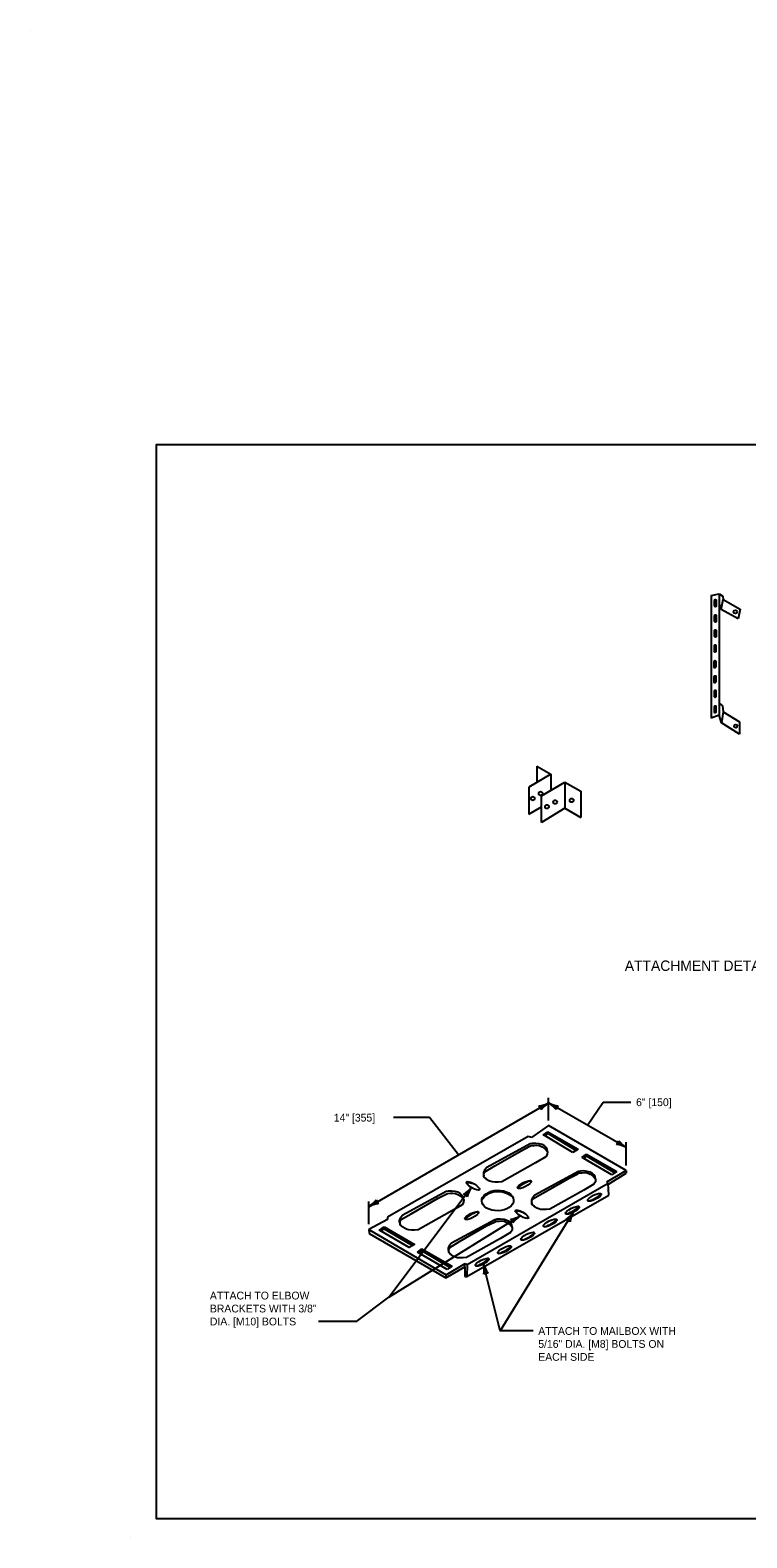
# Model space of a CAD drawing. Extents: x 49991.4 to 50021, y 49987.6 to 50011.4.
# Drawn here: x 50008.76 to 50014.29, y 49999.74 to 50011.36 of the extents above; entities that cross this region are included whole.
import ezdxf

# ---------------------------------------------------------------- set-up
doc = ezdxf.new("R2010")
doc.units = 0
for name, color, linetype in [('Level 1', 7, 'Continuous'), ('Level 2', 7, 'Continuous'), ('Level 3', 7, 'Continuous')]:
    doc.layers.add(name, color=color, linetype=linetype)

# ---------------------------------------------------------------- blocks, each defined once
blk = doc.blocks.new('ARR')
at = {"layer": 'Level 3'}
for centre, radius, start, end in [((1.5, 37), 37.1, 247.456, 267.6395), ((-21.4, 0), 9.13, 342.1388, 17.8612), ((1.9, -38.8), 38.8, 92.8273, 112.0772)]:
    blk.add_arc(centre, radius, start, end, dxfattribs=at)

msp = doc.modelspace()

# ---------------------------------------------------------------- linework, layer by layer
at = {"layer": 'Level 1'}
for p, q in [((50008.765, 50011.363), (50008.765, 50011.363)), ((50014.013, 50007.003), (50014.076, 50007.015)), ((50014.013, 50007.003), (50014.013, 50006.056)), ((50014.076, 50007.015), (50014.076, 50006.079)), ((50014.076, 50007.015), (50014.104, 50006.998)), ((50014.091, 50006.894), (50014.105, 50006.973)), ((50014.104, 50006.998), (50014.105, 50006.973)), ((50014.105, 50006.973), (50014.238, 50006.898)), ((50014.095, 50006.917), (50014.076, 50006.929)), ((50014.221, 50006.824), (50014.091, 50006.894)), ((50014.238, 50006.898), (50014.221, 50006.824)), ((50014.076, 50006.172), (50014.101, 50006.151)), ((50014.101, 50006.151), (50014.106, 50006.105)), ((50014.076, 50006.079), (50014.013, 50006.056)), ((50014.092, 50006.02), (50014.076, 50006.079)), ((50014.106, 50006.105), (50014.092, 50006.02)), ((50014.106, 50006.105), (50014.231, 50006.028)), ((50014.231, 50005.933), (50014.092, 50006.02)), ((50014.231, 50006.028), (50014.231, 50005.933)), ((50012.67, 50005.688), (50012.67, 50005.563)), ((50012.67, 50005.688), (50012.779, 50005.626)), ((50012.779, 50005.626), (50012.608, 50005.526)), ((50012.779, 50005.626), (50012.779, 50005.501)), ((50012.608, 50005.526), (50012.608, 50005.316)), ((50012.707, 50005.459), (50012.885, 50005.563)), ((50012.707, 50005.252), (50012.707, 50005.459)), ((50012.885, 50005.563), (50012.885, 50005.362)), ((50012.885, 50005.563), (50013.008, 50005.494)), ((50013.008, 50005.494), (50013.008, 50005.292)), ((50012.608, 50005.316), (50012.707, 50005.373)), ((50012.885, 50005.362), (50012.707, 50005.252)), ((50012.885, 50005.362), (50013.008, 50005.292)), ((50012.76, 50002.915), (50012.628, 50002.822)), ((50013.359, 50002.568), (50012.76, 50002.915)), ((50012.602, 50002.832), (50011.518, 50002.209)), ((50012.628, 50002.822), (50012.602, 50002.832)), ((50012.719, 50002.842), (50012.754, 50002.868)), ((50012.733, 50002.835), (50012.719, 50002.842)), ((50012.733, 50002.835), (50012.756, 50002.853)), ((50012.948, 50002.708), (50012.733, 50002.835)), ((50012.754, 50002.868), (50012.988, 50002.733)), ((50012.756, 50002.853), (50012.754, 50002.868)), ((50012.756, 50002.853), (50012.974, 50002.724)), ((50012.988, 50002.733), (50012.948, 50002.708)), ((50013.018, 50002.668), (50013.053, 50002.694)), ((50013.032, 50002.661), (50013.018, 50002.668)), ((50013.032, 50002.661), (50013.054, 50002.679)), ((50013.247, 50002.534), (50013.032, 50002.661)), ((50013.053, 50002.694), (50013.286, 50002.56)), ((50013.054, 50002.679), (50013.053, 50002.694)), ((50013.054, 50002.679), (50013.272, 50002.55)), ((50013.209, 50002.482), (50013.359, 50002.568)), ((50013.221, 50002.464), (50013.359, 50002.547)), ((50013.286, 50002.56), (50013.247, 50002.534)), ((50013.359, 50002.568), (50013.359, 50002.547)), ((50012.132, 50001.843), (50013.22, 50002.47)), ((50013.22, 50002.47), (50013.209, 50002.482)), ((50013.226, 50002.379), (50013.22, 50002.47)), ((50012.13, 50001.752), (50013.226, 50002.379)), ((50011.518, 50002.209), (50011.518, 50002.19)), ((50011.518, 50002.19), (50011.375, 50002.114)), ((50011.375, 50002.114), (50011.97, 50001.764)), ((50011.375, 50002.114), (50011.378, 50002.083)), ((50011.378, 50002.083), (50011.969, 50001.74)), ((50011.494, 50002.119), (50011.712, 50001.99)), ((50011.749, 50001.939), (50011.784, 50001.964)), ((50011.784, 50001.964), (50012.017, 50001.83)), ((50011.763, 50001.932), (50011.749, 50001.939)), ((50011.978, 50001.805), (50011.763, 50001.932)), ((50011.785, 50001.95), (50012.003, 50001.821)), ((50011.97, 50001.764), (50012.118, 50001.852)), ((50012.114, 50001.826), (50012.118, 50001.852)), ((50012.118, 50001.852), (50012.132, 50001.843)), ((50011.969, 50001.74), (50012.114, 50001.826)), ((50011.969, 50001.74), (50011.97, 50001.764)), ((50012.017, 50001.83), (50011.978, 50001.805)), ((50012.114, 50001.826), (50012.114, 50001.752)), ((50012.114, 50001.752), (50012.13, 50001.752)), ((50012.132, 50001.843), (50012.13, 50001.752)), ((50009.537, 49999.736), (50009.537, 49999.736))]:
    msp.add_line(p, q, dxfattribs=at)
for points in [[(50020.938, 50008.165), (50009.737, 50008.165), (50009.737, 49999.886), (50020.938, 49999.886)], [(50014.047, 50006.969), (50014.041, 50006.969), (50014.038, 50006.962), (50014.038, 50006.951), (50014.038, 50006.938), (50014.038, 50006.927), (50014.039, 50006.921), (50014.043, 50006.919), (50014.048, 50006.919), (50014.05, 50006.92), (50014.054, 50006.921), (50014.055, 50006.926), (50014.055, 50006.935), (50014.055, 50006.964), (50014.055, 50006.967), (50014.053, 50006.968), (50014.052, 50006.968), (50014.05, 50006.969), (50014.049, 50006.969)], [(50014.047, 50006.851), (50014.041, 50006.851), (50014.038, 50006.844), (50014.038, 50006.833), (50014.038, 50006.82), (50014.038, 50006.809), (50014.039, 50006.803), (50014.043, 50006.801), (50014.048, 50006.801), (50014.05, 50006.802), (50014.054, 50006.803), (50014.055, 50006.808), (50014.055, 50006.817), (50014.055, 50006.846), (50014.055, 50006.849), (50014.053, 50006.85), (50014.052, 50006.85), (50014.05, 50006.851), (50014.049, 50006.851)], [(50014.047, 50006.736), (50014.041, 50006.735), (50014.038, 50006.729), (50014.038, 50006.717), (50014.038, 50006.704), (50014.038, 50006.693), (50014.039, 50006.687), (50014.043, 50006.685), (50014.048, 50006.685), (50014.05, 50006.686), (50014.054, 50006.687), (50014.055, 50006.692), (50014.055, 50006.701), (50014.055, 50006.73), (50014.055, 50006.733), (50014.053, 50006.734), (50014.052, 50006.734), (50014.05, 50006.735), (50014.049, 50006.736)], [(50014.045, 50006.62), (50014.039, 50006.619), (50014.036, 50006.613), (50014.036, 50006.601), (50014.036, 50006.589), (50014.036, 50006.578), (50014.037, 50006.572), (50014.041, 50006.569), (50014.045, 50006.569), (50014.048, 50006.57), (50014.052, 50006.572), (50014.053, 50006.576), (50014.053, 50006.586), (50014.053, 50006.614), (50014.053, 50006.617), (50014.05, 50006.618), (50014.05, 50006.619), (50014.048, 50006.619), (50014.047, 50006.62)], [(50014.043, 50006.498), (50014.037, 50006.497), (50014.034, 50006.491), (50014.034, 50006.479), (50014.034, 50006.466), (50014.034, 50006.455), (50014.035, 50006.45), (50014.039, 50006.447), (50014.043, 50006.447), (50014.046, 50006.448), (50014.05, 50006.45), (50014.051, 50006.454), (50014.051, 50006.463), (50014.051, 50006.492), (50014.051, 50006.495), (50014.049, 50006.496), (50014.048, 50006.496), (50014.046, 50006.497), (50014.045, 50006.498)], [(50014.043, 50006.382), (50014.037, 50006.381), (50014.034, 50006.375), (50014.034, 50006.363), (50014.034, 50006.351), (50014.034, 50006.34), (50014.035, 50006.334), (50014.039, 50006.331), (50014.043, 50006.331), (50014.046, 50006.332), (50014.05, 50006.334), (50014.051, 50006.338), (50014.051, 50006.348), (50014.051, 50006.376), (50014.051, 50006.38), (50014.049, 50006.38), (50014.048, 50006.381), (50014.046, 50006.381), (50014.045, 50006.382)], [(50014.045, 50006.271), (50014.039, 50006.27), (50014.037, 50006.264), (50014.037, 50006.252), (50014.037, 50006.239), (50014.037, 50006.228), (50014.037, 50006.223), (50014.042, 50006.22), (50014.046, 50006.22), (50014.049, 50006.221), (50014.052, 50006.223), (50014.053, 50006.227), (50014.053, 50006.237), (50014.053, 50006.265), (50014.053, 50006.268), (50014.051, 50006.269), (50014.05, 50006.27), (50014.049, 50006.27), (50014.048, 50006.271)], [(50014.045, 50006.15), (50014.039, 50006.15), (50014.037, 50006.143), (50014.037, 50006.132), (50014.037, 50006.119), (50014.037, 50006.108), (50014.037, 50006.102), (50014.042, 50006.1), (50014.046, 50006.1), (50014.049, 50006.1), (50014.052, 50006.102), (50014.053, 50006.107), (50014.053, 50006.116), (50014.053, 50006.144), (50014.053, 50006.148), (50014.051, 50006.149), (50014.05, 50006.149), (50014.049, 50006.15), (50014.048, 50006.15)], [(50011.492, 50002.133), (50011.726, 50001.999), (50011.686, 50001.974), (50011.471, 50002.101), (50011.457, 50002.108)]]:
    msp.add_lwpolyline(points, close=True, dxfattribs=at)
for points in [[(50012.752, 50002.716), (50012.747, 50002.741), (50012.728, 50002.758), (50012.711, 50002.768), (50012.689, 50002.774), (50012.663, 50002.778), (50012.635, 50002.776), (50012.619, 50002.773), (50012.285, 50002.591), (50012.266, 50002.571), (50012.258, 50002.553), (50012.258, 50002.543), (50012.262, 50002.525)], [(50012.262, 50002.545), (50012.27, 50002.559), (50012.346, 50002.604), (50012.555, 50002.724), (50012.615, 50002.755), (50012.626, 50002.761), (50012.65, 50002.762), (50012.668, 50002.763), (50012.688, 50002.761), (50012.71, 50002.751), (50012.734, 50002.736), (50012.752, 50002.716), (50012.75, 50002.692), (50012.739, 50002.674), (50012.66, 50002.628), (50012.4, 50002.481), (50012.372, 50002.478), (50012.347, 50002.478), (50012.327, 50002.48), (50012.315, 50002.483), (50012.299, 50002.49), (50012.281, 50002.5), (50012.276, 50002.506), (50012.262, 50002.519), (50012.262, 50002.545)], [(50013.122, 50002.505), (50013.117, 50002.529), (50013.099, 50002.546), (50013.081, 50002.556), (50013.059, 50002.562), (50013.033, 50002.566), (50013.006, 50002.564), (50012.99, 50002.561), (50012.655, 50002.379), (50012.637, 50002.359), (50012.628, 50002.341), (50012.628, 50002.331), (50012.632, 50002.308)], [(50012.632, 50002.335), (50012.64, 50002.349), (50012.717, 50002.394), (50012.925, 50002.512), (50012.985, 50002.544), (50012.997, 50002.55), (50013.02, 50002.551), (50013.038, 50002.552), (50013.058, 50002.55), (50013.081, 50002.541), (50013.105, 50002.525), (50013.122, 50002.505), (50013.121, 50002.482), (50013.109, 50002.463), (50013.031, 50002.417), (50012.77, 50002.27), (50012.742, 50002.267), (50012.718, 50002.267), (50012.698, 50002.269), (50012.686, 50002.272), (50012.669, 50002.279), (50012.652, 50002.289), (50012.646, 50002.295), (50012.632, 50002.308), (50012.632, 50002.335)], [(50012.625, 50002.488), (50012.619, 50002.487), (50012.609, 50002.486), (50012.6, 50002.483), (50012.587, 50002.476), (50012.57, 50002.467), (50012.554, 50002.458), (50012.534, 50002.445), (50012.527, 50002.437), (50012.524, 50002.432)], [(50012.104, 50002.349), (50012.098, 50002.374), (50012.08, 50002.391), (50012.062, 50002.401), (50012.04, 50002.407), (50012.014, 50002.41), (50011.987, 50002.409), (50011.971, 50002.406), (50011.637, 50002.224), (50011.618, 50002.204), (50011.61, 50002.186), (50011.61, 50002.176), (50011.617, 50002.149)], [(50011.617, 50002.176), (50011.625, 50002.19), (50011.701, 50002.235), (50011.909, 50002.356), (50011.97, 50002.386), (50011.982, 50002.391), (50012.005, 50002.393), (50012.023, 50002.394), (50012.043, 50002.391), (50012.065, 50002.382), (50012.09, 50002.367), (50012.107, 50002.346), (50012.105, 50002.323), (50012.094, 50002.305), (50012.015, 50002.258), (50011.755, 50002.111), (50011.727, 50002.109), (50011.703, 50002.109), (50011.682, 50002.111), (50011.67, 50002.114), (50011.654, 50002.12), (50011.637, 50002.131), (50011.631, 50002.137), (50011.617, 50002.149), (50011.617, 50002.176)], [(50012.245, 50002.336), (50012.254, 50002.353), (50012.266, 50002.367), (50012.278, 50002.378), (50012.298, 50002.391), (50012.31, 50002.397), (50012.325, 50002.402), (50012.349, 50002.406), (50012.386, 50002.406), (50012.412, 50002.402), (50012.437, 50002.393), (50012.456, 50002.384), (50012.469, 50002.376), (50012.485, 50002.363)], [(50013.064, 50002.334), (50013.07, 50002.335), (50013.08, 50002.336), (50013.089, 50002.339), (50013.102, 50002.345), (50013.119, 50002.354), (50013.135, 50002.364), (50013.155, 50002.377), (50013.162, 50002.384), (50013.165, 50002.39)], [(50012.481, 50002.132), (50012.474, 50002.158), (50012.456, 50002.174), (50012.439, 50002.184), (50012.417, 50002.19), (50012.391, 50002.194), (50012.363, 50002.193), (50012.347, 50002.189), (50012.013, 50002.007), (50011.994, 50001.988), (50011.986, 50001.969), (50011.986, 50001.96), (50011.991, 50001.935)], [(50012.219, 50002.249), (50012.213, 50002.248), (50012.204, 50002.247), (50012.194, 50002.244), (50012.181, 50002.238), (50012.164, 50002.229), (50012.148, 50002.219), (50012.129, 50002.206), (50012.121, 50002.199), (50012.118, 50002.193)], [(50012.893, 50002.235), (50012.898, 50002.235), (50012.908, 50002.237), (50012.917, 50002.24), (50012.93, 50002.246), (50012.947, 50002.255), (50012.963, 50002.264), (50012.983, 50002.278), (50012.99, 50002.285), (50012.993, 50002.291)], [(50011.471, 50002.101), (50011.494, 50002.119), (50011.492, 50002.133)], [(50011.991, 50001.962), (50011.999, 50001.976), (50012.075, 50002.021), (50012.283, 50002.141), (50012.344, 50002.171), (50012.356, 50002.177), (50012.379, 50002.179), (50012.397, 50002.18), (50012.417, 50002.177), (50012.439, 50002.168), (50012.464, 50002.153), (50012.481, 50002.132), (50012.479, 50002.109), (50012.468, 50002.09), (50012.389, 50002.044), (50012.129, 50001.897), (50012.101, 50001.895), (50012.077, 50001.895), (50012.056, 50001.896), (50012.044, 50001.899), (50012.028, 50001.906), (50012.011, 50001.917), (50012.005, 50001.922), (50011.991, 50001.935), (50011.991, 50001.962)], [(50012.55, 50002.033), (50012.554, 50002.033), (50012.564, 50002.034), (50012.573, 50002.037), (50012.587, 50002.044), (50012.604, 50002.053), (50012.62, 50002.062), (50012.639, 50002.076), (50012.647, 50002.083), (50012.65, 50002.089)], [(50012.723, 50002.135), (50012.728, 50002.136), (50012.738, 50002.137), (50012.747, 50002.14), (50012.761, 50002.146), (50012.778, 50002.155), (50012.794, 50002.164), (50012.813, 50002.178), (50012.821, 50002.185), (50012.824, 50002.191)], [(50011.763, 50001.932), (50011.785, 50001.95), (50011.784, 50001.964)], [(50012.369, 50001.929), (50012.375, 50001.93), (50012.385, 50001.931), (50012.394, 50001.934), (50012.407, 50001.941), (50012.424, 50001.95), (50012.44, 50001.959), (50012.46, 50001.973), (50012.467, 50001.98), (50012.47, 50001.985)], [(50012.197, 50001.833), (50012.202, 50001.834), (50012.212, 50001.835), (50012.222, 50001.838), (50012.235, 50001.845), (50012.252, 50001.854), (50012.268, 50001.863), (50012.287, 50001.876), (50012.295, 50001.884), (50012.298, 50001.889)]]:
    msp.add_lwpolyline(points, dxfattribs=at)
for centre, radius in [((50014.2, 50006.877), 0.0131), ((50014.203, 50005.996), 0.0131), ((50012.639, 50005.437), 0.0146), ((50012.699, 50005.476), 0.0146), ((50012.748, 50005.374), 0.0146), ((50012.811, 50005.41), 0.0146), ((50012.938, 50005.423), 0.0146)]:
    msp.add_circle(centre, radius, dxfattribs=at)
for centre, major_axis, ratio in [((50012.177, 50002.45), (-0.0504, 0.0292), 0.298197), ((50012.574, 50002.46), (-0.052, -0.0263), 0.298197), ((50012.368, 50002.337), (0.123, 0.004), 0.639715), ((50013.115, 50002.362), (0.052, 0.0263), 0.298197), ((50012.168, 50002.221), (-0.052, -0.0263), 0.298197), ((50012.554, 50002.231), (-0.0504, 0.0292), 0.298197), ((50012.773, 50002.164), (0.052, 0.0263), 0.298197), ((50012.944, 50002.262), (0.052, 0.0263), 0.298197), ((50012.599, 50002.062), (0.052, 0.0263), 0.298197), ((50012.42, 50001.957), (0.052, 0.0263), 0.298197), ((50012.248, 50001.861), (0.052, 0.0263), 0.298197)]:
    msp.add_ellipse(centre, major_axis=major_axis, ratio=ratio, dxfattribs=at)
for points in [[(50012.145, 50002.451), (50012.131, 50002.473), (50012.134, 50002.481), (50012.181, 50002.468)], [(50012.52, 50002.235), (50012.513, 50002.251), (50012.517, 50002.264), (50012.558, 50002.249)]]:
    msp.add_open_spline(points, degree=2, dxfattribs=at)
at = {"layer": 'Level 3'}
for p, q in [((50012.76, 50002.955), (50012.76, 50003.13)), ((50011.375, 50002.289), (50012.76, 50003.09)), ((50013.359, 50002.746), (50012.76, 50003.09)), ((50013.061, 50002.917), (50013.181, 50003.095)), ((50013.181, 50003.095), (50013.395, 50003.095)), ((50011.842, 50002.976), (50011.564, 50002.976)), ((50012.067, 50002.689), (50011.842, 50002.976)), ((50013.359, 50002.608), (50013.359, 50002.786)), ((50011.53, 50001.592), (50012.164, 50002.437)), ((50011.375, 50002.154), (50011.375, 50002.329)), ((50011.53, 50001.592), (50012.541, 50002.219)), ((50011.28, 50001.404), (50011.53, 50001.592)), ((50011.28, 50001.404), (50010.987, 50001.404)), ((50012.641, 50001.331), (50012.387, 50001.331))]:
    msp.add_line(p, q, dxfattribs=at)
msp.add_lwpolyline([(50012.951, 50002.247), (50012.387, 50001.331), (50012.259, 50001.847)], dxfattribs=at)

# ---------------------------------------------------------------- block references
for p, xscale, yscale, rotation in [((50012.76, 50003.09), 0.005999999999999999, 0.006, 30.053473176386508), ((50012.76, 50003.09), 0.006, 0.006, 150.1729056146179), ((50013.359, 50002.746), 0.006, 0.006, -29.827094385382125), ((50012.164, 50002.437), 0.006000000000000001, 0.006, 53.10968555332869), ((50011.375, 50002.289), 0.005999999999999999, 0.006, -149.9465268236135), ((50012.541, 50002.219), 0.006, 0.006000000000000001, 31.798451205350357), ((50012.951, 50002.247), 0.006, 0.006000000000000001, 58.362674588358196), ((50012.259, 50001.847), 0.006, 0.006, 103.89956102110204)]:
    msp.add_blockref('ARR', p, dxfattribs=dict(at, xscale=xscale, yscale=yscale, rotation=rotation))

# ---------------------------------------------------------------- texts
at = {"layer": 'Level 2'}
for s, height, p in [('ATTACHMENT DETAILS', 0.08, (50013.348, 50004.108)), ('6" [150]', 0.06, (50013.435, 50003.065)), ('14" [355]', 0.06, (50011.105, 50002.946)), ('ATTACH TO ELBOW', 0.06, (50010.15, 50001.574)), ('BRACKETS WITH 3/8"', 0.06, (50010.15, 50001.474)), ('DIA. [M10] BOLTS', 0.06, (50010.15, 50001.374)), ('ATTACH TO MAILBOX WITH', 0.06, (50012.681, 50001.301)), ('5/16" DIA. [M8] BOLTS ON ', 0.06, (50012.681, 50001.201)), ('EACH SIDE', 0.06, (50012.681, 50001.101))]:
    msp.add_text(s, height=height, dxfattribs=at).set_placement(p)

doc.saveas('drawing.dxf')
